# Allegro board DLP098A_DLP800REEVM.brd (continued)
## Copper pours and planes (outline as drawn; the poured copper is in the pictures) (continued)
VRESET_RAIL on TOP: 110.58,31.34 111.9,31.34 112.03,31.2 112.03,27.46 111.98,27.4 111.47,27.4 110.52,26.46 107.02,26.46 106.27,27.21 106.27,27.84 106.89,28.46 110.3,28.46 110.47,28.63 110.47,31.23
VRESET_RAIL on TOP: 84.49,35.84 84.49,33.65 84.74,33.4 84.74,23.28 84.49,23.04 84.49,20.84 84.57,20.76 85.25,20.76 85.31,20.81 85.31,23.5 85.7,23.89 89.04,23.89 89.5,23.43 89.5,20.85 89.52,20.83 90.29,20.83 90.31,20.85 90.31,35.84 90.31,35.85 89.5,35.85 89.5,35.84 89.5,33.61 88.89,33 85.88,33 85.32,33.56 85.32,35.85 85.28,35.89 84.53,35.89
VRESET_RAIL on 10_SIG4: 85.07,26.14 106.53,26.14 107.67,27.28 107.67,29.44 106.02,31.09 85.32,31.09 84.81,30.58 84.81,26.39
N16551414 on TOP: 103.53,22.02 99.77,22.02 96.98,24.82 96.98,26.85 96.48,27.36 96.04,27.36 95.89,27.2 95.89,27 96.07,26.82 96.07,22.15 100.89,17.32 106.72,17.32 107.24,17.84 107.24,21.91 106.39,22.76 104.26,22.76
N16555452 on TOP: 95.07,28.24 96.45,28.24 96.75,28.55 100.56,28.55 102.47,26.64 106.26,26.64 106.4,26.5 106.4,25.17 106.33,25.1 99.06,25.1 98.68,25.48 98.68,26.37 98.28,26.77 97.26,26.77 96.49,27.53 95.3,27.53 95.05,27.79 95.05,28.22
N16558116 on TOP: 95.33,28.93 96.32,28.93 96.19,28.8 98.4,28.8 100.05,30.45 100.05,31.72 100.43,32.11 104.37,32.11 104.37,33.12 102.21,35.28 101.07,35.28 101.07,34.26 96.12,29.31 95.23,29.31 95.15,29.24 95.15,29.11
N16949505 on TOP: 117.58,10.26 115.67,10.26 114.91,11.02 110.47,11.02 109.07,12.42 109.07,21.67 109.31,21.91 111.81,21.91 111.99,21.73 111.99,13.95 113.26,12.67 116.05,12.67 117.58,11.15

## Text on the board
BOTTOM: 12_BOTTOM
Ref Des/Assembly Bottom: ASSEMBLY
Ref Des/Silkscreen Bottom: FEB-2023 | 305-PD-22-1008 | SILK-BOTTOM
User.Comments: MASK-BOTTOM
TOP: 01_TOP
Ref Des/Assembly Top: ASSEMBLY
Board Geometry/Soldermask Top: MASK-TOP
Ref Des/Silkscreen Top: NOT FCC APPROVED FOR RESALE. | FOR EVALUATION ONLY. | 8 | 9 | 7 | 6 | 10 | MBRST | 5 | 4 | 12 | 3 | 11 | 14 | 2 | 1 | 13 | 15 | 0 | P1V8 | MODEB | VBIAS | V_OFFSET | VCC2_EN | VRESET_DAD | VCC2 | VRESET_EXT | VRESET_RAIL | VR_PG | SILK-TOP | TEXAS INSTRUMENTS, INC.
02_GND1: 02_GND1
03_SIG1: 03_SIG1
04_GND2: 04_GND2
05_SIG2: 05_SIG2
06_PWR1: 06_PWR1
07_PWR2: 07_PWR2
08_SIG3: 08_SIG3
09_GND3: 09_GND3
10_SIG4: 10_SIG4
11_GND4: 11_GND4
DIMENSION: FAB
User.13: NEED TO CUT THIS REGION | 4.25 MIL LINES WITH 5.75 MIL SPACES ON INNER LAYER = 100 OHMS DIFFERENTIAL IMPEDANCE +/-10% | 4.2 MIL LINES WITH 5 MIL SPACES ON OUTER LAYER = 100 OHMS DIFFERENTIAL IMPEDANCE +/-10% | x4 LOCATION | 7.50 MIL LINES ON THE OUTER LAYERS = 50 OHMS SINGLE ENDED IMPEDANCE +/-10% | 5.25 MIL LINES ON THE INNER LAYERS = 50 OHMS SINGLE ENDED IMPEDANCE +/-10% | ***CONTROLLED IMPEDANCE DESIGN*** | 2 | 10 | 9 | 10. NO VENDOR LOGO, ART WORKS SHOULD NOT BE CHANGED WITHOUT PRIOR APPROVAL FROM TEXAS INSTRUMENTS | 10. MARKED REGION VIAS NEED TO BE SOLDERMASK PLUGGING ON TOP SIDE | 2. PLATE INDICATED AREAS WITH A MIN 30 MICROINCHES | ELECTROLYTIC GOLD OVER A MIN 150 MICROINCHES | ELECTROLYTIC NICKEL. | 9. ALL HOLES IN DRILL CHART ARE FINISHED HOLE SIZES (FHS). | 6. TEARDROPS SHOULD NOT BE ADDED ON ANY AREA WITHOUT PRIOR APPROVAL FROM TEXAS INSTRUMENTS | 7. DEBURR ALL SHARP EDGES | 8. REMOVE UNUSED PADS IN ALL INNER LAYERS | 9. MARKED REGION VIAS NEED TO BE SOLDERMASK PLUGGING ON BOTTOM SIDE | 1. ALL DIMENSIONS ARE IN INCHES UNLESS | OTHERWISE NOTED. | 4. FABRICATION VENDOR IS ALLOWED TO INCREASE SOLDERMASK | COMPONENT PADS BY A MAXIMUM 1 MIL ON EACH SIDE OVER | THE COPPER PAD IN ORDER TO MEET TOOLING REQUIREMENTS | WHILE MAINTAINING WEBBING BETWEEN ADJACENT PADS.
User.14: A | k | 1 | 40 | 22 | J14 | 10 | 2 | 4 | 3 | J15 | 6 | TP63 | 21 | J4 | TP26 | TP27 | TP29 | 19 | J48 | TP28 | J40 | TP30 | R62 | R52 | R51 | C38 | R50 | R49 | TP31 | 20 | R63 | R55 | R54 | J5 | C9 | 12 | J54 | J42 | U13 | C10 | J50 | TP64 | TP51 | C11 | TP52 | J6 | J1 | J43 | J20 | R8 | 60 | J49 | 59 | J44 | TP53 | U14 | 62 | 61 | TP50 | SW1 | J28 | PARK | RUN | U4 | VR1 | TP59 | J63 | J55 | J57 | 5 | J2 | J24 | TP62 | J21 | J29 | TP46 | R15 | TP12 | TP13 | VR2 | 120 | TP47 | 119 | TP48 | R56 | J25 | U11 | TP38 | J56 | TP49 | TP24 | TP21 | TP18 | U18 | TP14 | D5 | TP19 | J37 | TP2 | R20 | TP16 | R71 | R41 | R57 | L6 | J26 | J30 | TP25 | D7 | J13 | TP17 | TP40 | J59 | J12 | L1 | R27 | J38 | L9 | R72 | TP32 | TP22 | R58 | D2 | C27 | L5 | R24 | D8 | J60 | R43 | C28 | C6 | R25 | C41 | L8 | R73 | TP15 | R59 | U19 | R6 | Q5 | J39 | J61 | D14 | D15 | D13 | R42 | C18 | R33 | U7 | R68 | R69 | R67 | R70 | R31 | Q3 | C21 | TP41 | D12 | R7 | L2 | C16 | R45 | R46 | R60 | L4 | U5 | R17 | L7 | J31 | J62 | Q4 | U20 | C32 | R47 | 18 | 13 | FB1 | J17 | R21 | R26 | J3 | U17 | C17 | R74 | U3 | U12 | D10 | 24 | 7 | U21 | R23 | TP20 | R22 | J22 | C42 | TP45 | U6 | J47 | J32 | U1 | U9 | C31 | C15 | U10 | Q1 | Q2 | 25 | 36 | 37 | U15 | U2 | 48 | C26 | C1 | U22 | TP4 | J52 | J53 | J58 | R65 | C40 | J18 | J33 | J19 | J34 | TP55 | J35 | TP56 | TP57 | TP58 | J41 | R53 | J23 | R64 | C2 | C3 | J8 | TP54 | J27 | 38 | U8 | J9 | J51 | J10 | R9 | 28 | J11 | R10 | R66 | J45 | R1 | TP5 | R11 | R2 | C4 | R12 | C5 | R13 | C12 | R14 | R44 | C13 | C14 | TP6 | TP60 | TP7 | TP61 | TP8 | TP37 | TP9 | FB2 | TP10 | C34 | TP11 | J46 | C35 | TP44 | R37 | R38 | C39 | R39 | FB3 | R3 | R40 | TP34 | J36 | R35 | TP1 | D1 | TP35 | R16 | TP39 | R28 | R36 | R4 | L3 | R5 | D4 | TP33 | TP3 | D6 | D3 | R32 | D9 | C29 | TP42 | C37 | TP43 | D11 | C19 | R34 | R61 | TP23 | R48 | C33 | C7 | C24 | C8 | C25 | 14 | R19 | C30 | R18 | J7 | C22 | C23 | U16 | C36 | C20 | TP36 | J16
User.20: LAYER 1 - PRIMARY SIDE
User.21: LAYER 2 - GND PLANE
User.22: LAYER 3 - SIGNAL
User.23: LAYER 4 - GND PLANE
User.24: LAYER 6 - VCC PLANE
User.25: LAYER 7 - VCC PLANE
User.26: LAYER 9 - GND PLANE
User.27: LAYER 10 - SIGNAL
User.28: LAYER 11 SIGNAL
User.29: LAYER 10 - SECONDARY SIDE
User.34: PASTE-TOP
User.35: PASTE-BOTTOM
User.45: FIGURE | SIZE | 7.874 | 12.0 | 28.0 | 63.0 | 165.402 | 50.0 | 125.0 | DRILL CHART: TOP to BOTTOM | ALL UNITS ARE IN MILS | TOLERANCE | +3.0/-3.0 | +2.0/-0.0 | PLATED | NON-PLATED | QTY | 20 | 1186 | 39 | 1 | 4 | 2 | 3 | DATE: FEB 2023 | PAC NUMBER: 305-PD-22-1008 | JOB NAME: DLP780NE_DLP800RE_DLP780TE | FILM LAYER: | CUSTOMER NAME : | STACKUP: 12 LAYERS | TOTAL THICKNESS: 67 mils +/-10% | DIELECTRIC (4.529 mils) | DIELECTRIC (5.906 mils) | DIELECTRIC (5.831 mils) | DIELECTRIC (2.992 mils) | TOP (0.5 oz + PLATING) | 02_GND1 (1 oz) | 03_SIG1 (0.5 oz) | 04_GND2 (1 oz) | 05_SIG2 (0.5 oz) | 06_PWR1 (1 oz) | 07_PWR2 (1 oz) | 08_SIG3 (0.5 oz) | 09_GND3 (1 oz) | 10_SIG4 (0.5 oz) | 11_GND4 (1 oz) | BOTTOM 0.5 oz + PLATING) | REV:1 | FR4-HTG | TEXAS INSTRUMENTS
